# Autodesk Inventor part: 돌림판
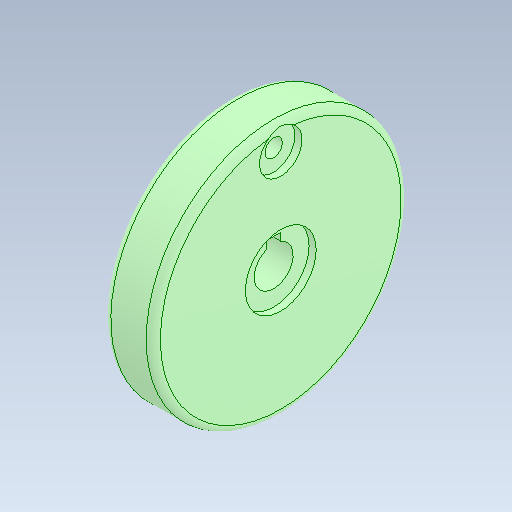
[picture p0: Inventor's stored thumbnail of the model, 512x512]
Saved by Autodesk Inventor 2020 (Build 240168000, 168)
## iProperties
Created: 2024-04
Part Number: 돌림판
Material: 일반
Document SubType Name: Modeling
Designer: oem
Density: 1 g/cm^3
Appearance: 기본값
Mass: 43.9175 g
Surface Area: 129.083 cm^2
Volume: 43.9175 cm^3
Sending System: Autodesk Inventor 2025
Preprocessor: ST-DEVELOPER v20
Author: jhkim
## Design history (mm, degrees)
feature "솔리드1"
node "솔리드2"
